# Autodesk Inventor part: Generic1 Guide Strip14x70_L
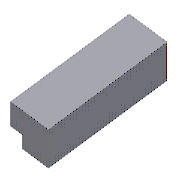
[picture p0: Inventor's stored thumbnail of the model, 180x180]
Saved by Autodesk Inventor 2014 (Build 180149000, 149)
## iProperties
IsCustomPart: 1
Created: 2009-11
Part Number: Generic1 Guide Strip14x70_L
Material: DIN 1.2842
Description: Guide Rail
Document SubType Name: Modeling
Designer: gaom
Standard Revision: 1
Manufacturer: Generic
Language: en-US
Size Designation: 14x70_L
Categories: <MemberInstance><Categories><Category DisplayName="Mold" InternalName="349578f2-f4d4-4954-8c09-8e99297a61c0" Mnemonic="MOLD"><Category DisplayName="Slide Compon
Density: 7.66 g/cm^3
Appearance: Polished - Brushed Heavy-1-1-1-1-1-1-1-1-1-1-1-1-1-1
Position: L
Part Type: 2
Author: gaom
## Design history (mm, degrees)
sketch "Sketch1"
  geometry: L1 (0, -6)-(0, 8) reference; L2 (-20, 6)-(-34, 6); L3 (-34, 6)-(-34, -4); L4 (-34, -4)-(-25, -4); L5 (-25, -4)-(-25, 0); L6 (-25, 0)-(-20, 0); L7 (-20, 0)-(-20, 6); 1 further point
  constraints: 12 end point, 3 horizontal, 3 vertical, 1 horizontal alignment
  dimensions: "d235" = 14 distance of L2.start L2.end (derived); "d236" = 10 distance of L2.end L3.end (derived); "d237" = 5 distance of L5.end L6.end (derived); "d238" = 4 distance of L4.end L5.end (derived); "d239" = 20 distance between parallel lines of L7 L1 (derived)
extrude "Extrusion_L" new body sketch "Sketch1" distance "d27" = 70 (= GS_l1); taper "d28" = 0 deg
sketch "Sketch4"
  geometry: L1 (20, 0)-(20, 6); L2 (20, 6)-(34, 6); L3 (34, 6)-(34, -4); L4 (34, -4)-(25, -4); L5 (25, -4)-(25, 0); L6 (20, 0)-(25, 0); L7 (0, 8)-(0, -6) reference; 1 further point
  constraints: 12 end point, 3 parallel, 1 horizontal, 1 horizontal alignment, 1 perpendicular, 1 vertical
  dimensions: "d101" = 10 distance between parallel lines of L4 L2 (= GS_h2); "d240" = 14 distance of L1.end L2.end (derived); "d241" = 4 distance of L4.end L5.end (derived); "d242" = 5 distance of L1.start L5.end (derived); "d243" = 20 distance between parallel lines of L1 L7 (derived)
extrude "Extrusion_R" new body sketch "Sketch4" distance "d107" = 70 (derived); taper "d108" = 0 deg
body "Solid1"
workplane "Work Plane1"
feature "Stitch Surface1" dims "d272" = 0.254 (derived)
workplane "Work Plane2"
feature "Stitch Surface2" dims "d273" = 0.254 (derived)
sketch "Sketch2"
  geometry: L1 (0, 14)-(0, 0); L2 (170, 14)-(170, 0); L3 (70, 0)-(70, 14) reference; L4 (0, 14)-(70, 14) reference; L5 (0, 0)-(70, 0) reference; L6 (0, 14)-(170, 14); L7 (0, 0)-(170, 0); 3 further points
  constraints: 8 end point, 3 point on line, 2 horizontal, 2 midpoint, 2 vertical
  dimensions: "d255" = 100 distance between parallel lines of L3 L2 (derived)
body "Srf1"
body "Srf2"
body "Srf3"
body "Srf4"
sketch "Sketch5"
  geometry: L1 (0, 14)-(170, 14); L2 (170, 14)-(170, 0); L3 (170, 0)-(0, 0); L4 (0, 0)-(0, 14); L5 (0, 14)-(70, 14) reference; L6 (70, 0)-(70, 14) reference; L7 (0, 0)-(70, 0) reference; 2 further points
  constraints: 8 end point, 6 point on line, 2 parallel, 1 collinear, 1 horizontal, 1 midpoint, 1 perpendicular
  dimensions: "d136" = 100 distance between parallel lines of L2 L6 (derived)
body "Srf5"
body "Srf6"
body "Srf7"
body "Srf8"
extrude_surface "ExtrusionSrf1" dims "d81" = 10.5 (derived), "d82" = 0
patch "Boundary Patch1" dims "d84" = 0, "d256" = 0, "d257" = 0, "d258" = 0, "d259" = 0
patch "Boundary Patch2" dims "d86" = 0, "d260" = 0, "d261" = 0, "d262" = 0, "d263" = 0
extrude_surface "ExtrusionSrf3" dims "d138" = 10.5 (derived), "d139" = 0
patch "Boundary Patch5" dims "d250" = 0, "d264" = 0, "d265" = 0, "d266" = 0, "d267" = 0
patch "Boundary Patch6" dims "d252" = 0, "d268" = 0, "d269" = 0, "d270" = 0, "d271" = 0
other parameters: "GS_b" = 14 [user parameter], "GS_l1" = 70 [user parameter; used in 1 equation term], "GS_h2" = 10 [user parameter; used in 1 equation term], "GS_t1" = 5 [user parameter], "GS_h3" = 4 [user parameter], "GS_es1" = 0.5 [user parameter; used in 1 equation term], "GS_esr" = 2.5 [user parameter], "GS_esw" = 5 [user parameter], "GS_esl1" = 5 [user parameter], "d96" = 0.5 (= GS_es1), "d134" = 0.5 (derived)
